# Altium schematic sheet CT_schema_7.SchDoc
size 287 x 160 mm
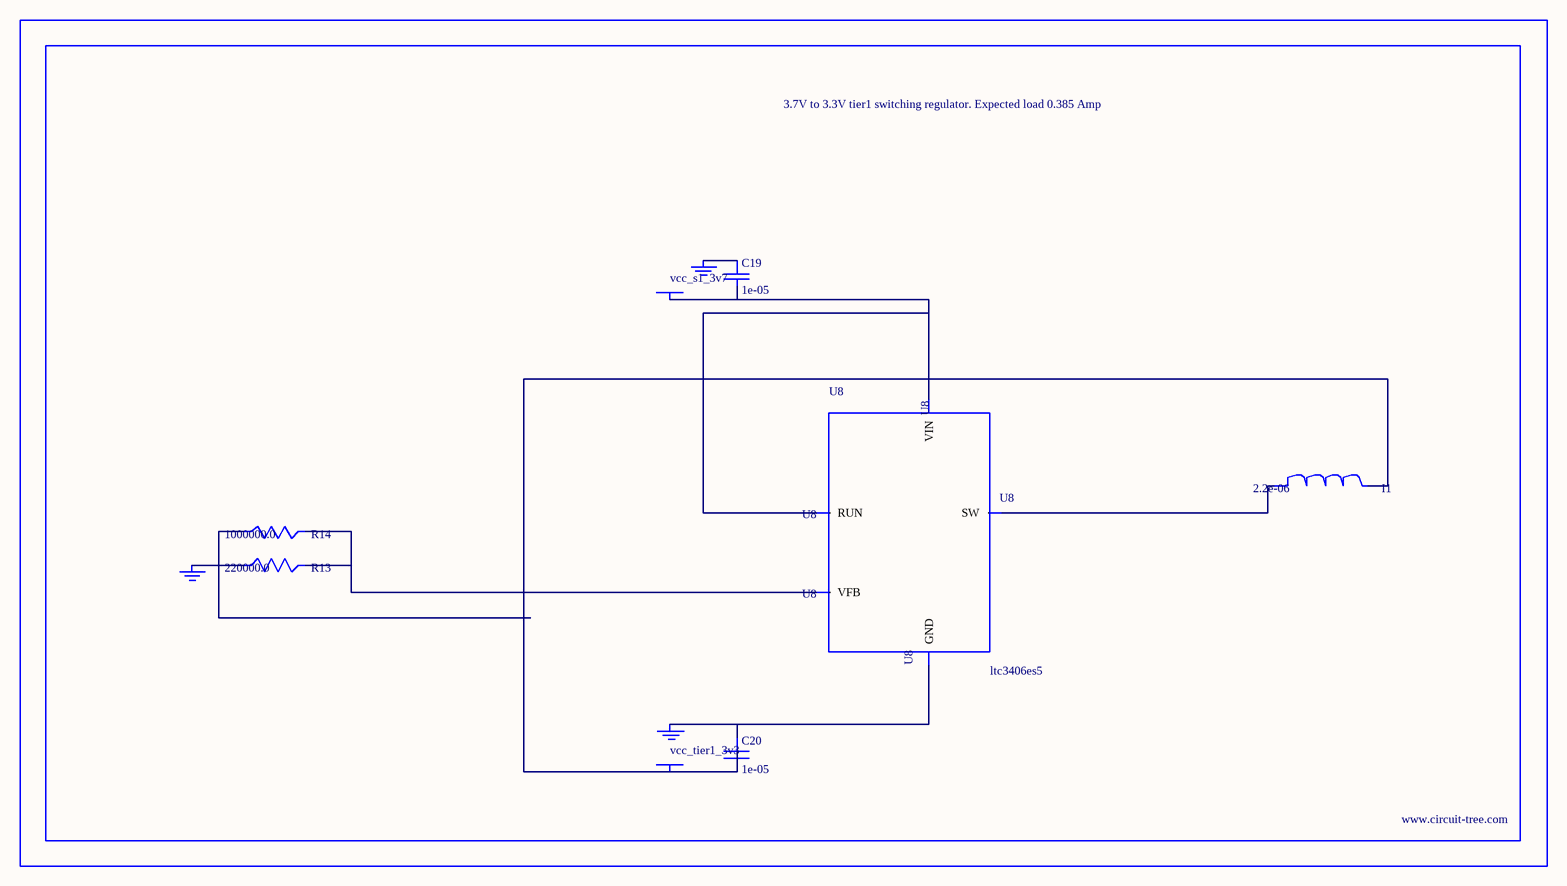
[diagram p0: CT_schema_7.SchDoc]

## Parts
BORDER6  (no value)
C19  1e-05  [C0805]
C20  1e-05  [C0805]
GND_INSTANCE_6_0  (no value)
GND_INSTANCE_6_1  (no value)
GND_INSTANCE_6_2  (no value)
I1  2.2e-06  [L0805]
POWER_INSTANCE_6_0  vcc_tier1_3v3
POWER_INSTANCE_6_1  vcc_s1_3v7
R13  220000.0  [R0603]
R14  1000000.0  [R0603]
U8  ltc3406es5  [TSOT-23-5]

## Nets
NetC19_1: C19.1 GND_INSTANCE_6_1.0(GND)
NetC19_2: C19.2 POWER_INSTANCE_6_1.0(PWR) U8.1(RUN) U8.4(VIN)
NetC20_1: C20.1 GND_INSTANCE_6_0.0(GND) U8.2(GND)
NetC20_2: C20.2 I1.2 POWER_INSTANCE_6_0.0(PWR) R14.1
NetGND_INSTANCE_6_2_0: GND_INSTANCE_6_2.0(GND) R13.1
NetI1_1: I1.1 U8.3(SW)
NetR13_2: R13.2 R14.2 U8.5(VFB)

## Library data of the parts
BORDER6 = BORDER_PAGE6
C19 C20 = C0805C106K8RACTU
GND_INSTANCE_6_0-GND_INSTANCE_6_2 = GND
I1 = L0805C2R2MDWIT
POWER_INSTANCE_6_0 POWER_INSTANCE_6_1 = PWR
R13 = RC0603JR-07220KL
R14 = RC0603JR-071ML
